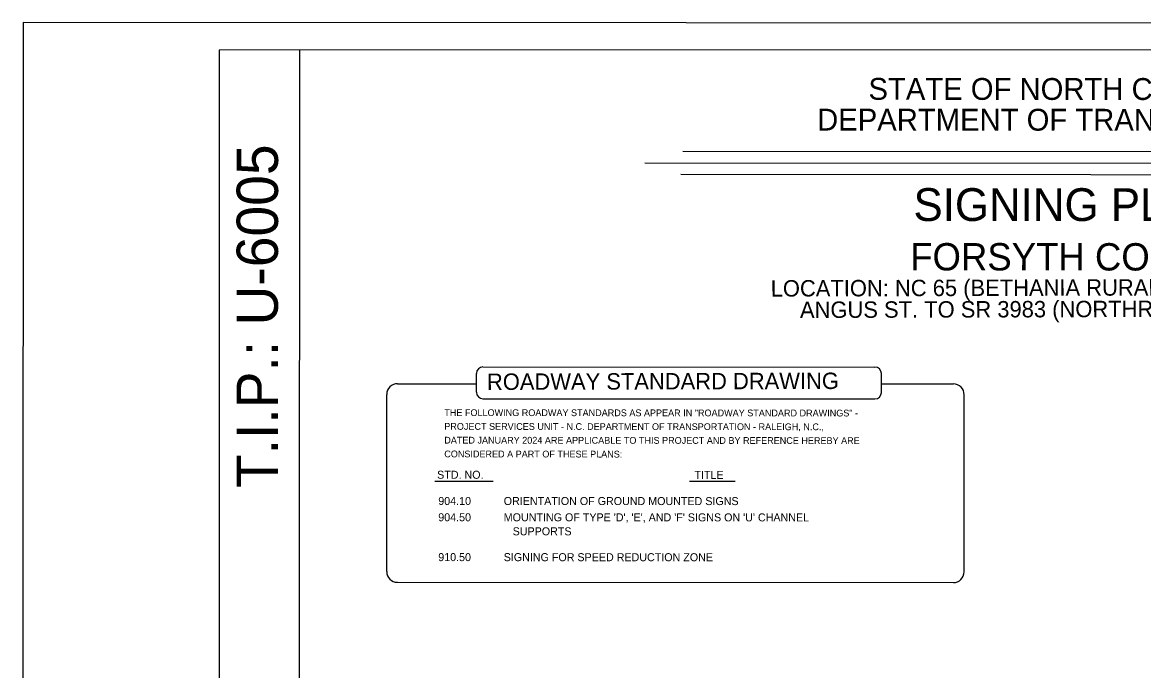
# Model space of a CAD drawing. Extents: x 50703 to 52785, y 49383 to 50479.
# Drawn here: x 50703 to 51651, y 49931 to 50479 of the extents above; entities that cross this region are included whole.
import ezdxf

# ---------------------------------------------------------------- set-up
doc = ezdxf.new("R2010")
doc.units = 0
for name, color, linetype in [('Default', 7, 'Continuous'), ('DEV TITLE SHEET CELL', 7, 'Continuous'), ('Old_Level_18', 7, 'Continuous'), ('Sheet Plot Border Outside CELL', 7, 'Continuous'), ('Sheet Title CELL', 7, 'Continuous')]:
    doc.layers.add(name, color=color, linetype=linetype)

msp = doc.modelspace()

# ---------------------------------------------------------------- linework, layer by layer
at = {"layer": 'Default'}
for points in [[(51261.15, 50370.27), (51954.95, 50369.95)], [(51229.19, 50360.53), (51983.6, 50360.18)], [(51259.46, 50350.77), (51953.26, 50350.44)]]:
    msp.add_lwpolyline(points, dxfattribs=at)
at = {"layer": 'Old_Level_18'}
msp.add_lwpolyline([(52369.04, 50455.98), (50869.05, 50455.87), (50869.12, 49405.87), (52369.12, 49405.98)], close=True, dxfattribs=at)
at = {"layer": 'Sheet Plot Border Outside CELL'}
msp.add_lwpolyline([(52386.04, 50478.48), (50703.13, 50479.27), (50702.62, 49383.36), (52385.53, 49382.58)], close=True, dxfattribs=at)
at = {"layer": 'Sheet Title CELL'}
for p, q in [((51086.72, 50166.36), (51086.73, 50182.39)), ((51429.27, 50166.2), (51429.28, 50182.23)), ((51019.93, 50173.61), (51086.73, 50173.58)), ((51429.27, 50173.42), (51490.21, 50173.39)), ((51010.77, 50014.69), (51010.84, 50164.53)), ((51499.23, 50014.46), (51499.3, 50164.3)), ((51051.59, 50091.26), (51100.84, 50091.23)), ((51266.81, 50091.16), (51305.65, 50091.14)), ((51019.85, 50005.6), (51490.14, 50005.38))]:
    msp.add_line(p, q, dxfattribs=at)
for points in [[(50936.87, 49405.88), (50937.36, 50455.88)], [(51092.19, 50187.84), (51423.83, 50187.68)], [(51092.17, 50160.91), (51423.81, 50160.75)]]:
    msp.add_lwpolyline(points, dxfattribs=at)
for centre, radius, start, end in [((51092.18, 50182.38), 5.45, 89.97341, 179.97341), ((51423.82, 50182.23), 5.45, 359.97341, 89.97341), ((51019.93, 50164.52), 9.09, 89.97341, 179.97341), ((51490.21, 50164.31), 9.09, 359.97341, 89.97341), ((51092.18, 50166.36), 5.45, 179.97341, 269.97341), ((51423.82, 50166.21), 5.45, 269.97341, 359.97341), ((51019.86, 50014.69), 9.09, 179.97341, 269.97341), ((51490.14, 50014.47), 9.09, 269.97341, 359.97341)]:
    msp.add_arc(centre, radius, start, end, dxfattribs=at)

# ---------------------------------------------------------------- texts
at = {"layer": 'Default'}
for s, height, rotation, p in [('STATE OF NORTH CAROLINA', 18.4936, 359.97341, (51418.32, 50413.79)), ('DEPARTMENT OF TRANSPORTATION', 18.4936, 359.97341, (51374.88, 50387.78)), ('T.I.P.: U-6005', 34.925, 89.97341, (50918.68, 50085.33)), ('SIGNING PLAN', 27.7403, 359.97341, (51456.39, 50311.3)), ('FORSYTH COUNTY', 23.1165, 359.97341, (51453.61, 50269.48)), ('LOCATION: NC 65 (BETHANIA RURAL HALL RD.) FROM', 13.8702, 0.15565, (51335.63, 50247.33)), ('ANGUS ST. TO SR 3983 (NORTHRIDGE PARK DR.)', 13.8702, 0.15565, (51360.38, 50229.21)), ('ROADWAY STANDARD DRAWING', 13.8661, 0.15565, (51095.63, 50168.35)), ('STD. NO.', 6.771, 359.97341, (51053.43, 50093.22)), ('TITLE', 6.771, 359.97341, (51271.09, 50093.12)), ('904.10           ORIENTATION OF GROUND MOUNTED SIGNS', 6.7709, 359.97341, (51054.41, 50071.03)), ("904.50           MOUNTING OF TYPE 'D', 'E', AND 'F' SIGNS ON 'U' CHANNEL", 6.7709, 359.97341, (51054.41, 50057.25)), ('           SUPPORTS', 6.7709, 359.97341, (51089.66, 50045.38)), ('910.50           SIGNING FOR SPEED REDUCTION ZONE', 6.7709, 359.97341, (51054.39, 50023.52))]:
    msp.add_text(s, height=height, rotation=rotation, dxfattribs=at).set_placement(p)
at = {"layer": 'DEV TITLE SHEET CELL'}
for s, p in [('THE FOLLOWING ROADWAY STANDARDS AS APPEAR IN "ROADWAY STANDARD DRAWINGS" -', (51059.51, 50146.31)), ('PROJECT SERVICES UNIT - N.C. DEPARTMENT OF TRANSPORTATION - RALEIGH, N.C.,', (51059.49, 50134.65)), ('DATED JANUARY 2024 ARE APPLICABLE TO THIS PROJECT AND BY REFERENCE HEREBY ARE ', (51059.48, 50123)), ('CONSIDERED A PART OF THESE PLANS:', (51059.47, 50111.34))]:
    msp.add_text(s, height=5.7256, rotation=359.93321, dxfattribs=at).set_placement(p)

doc.saveas('drawing.dxf')
